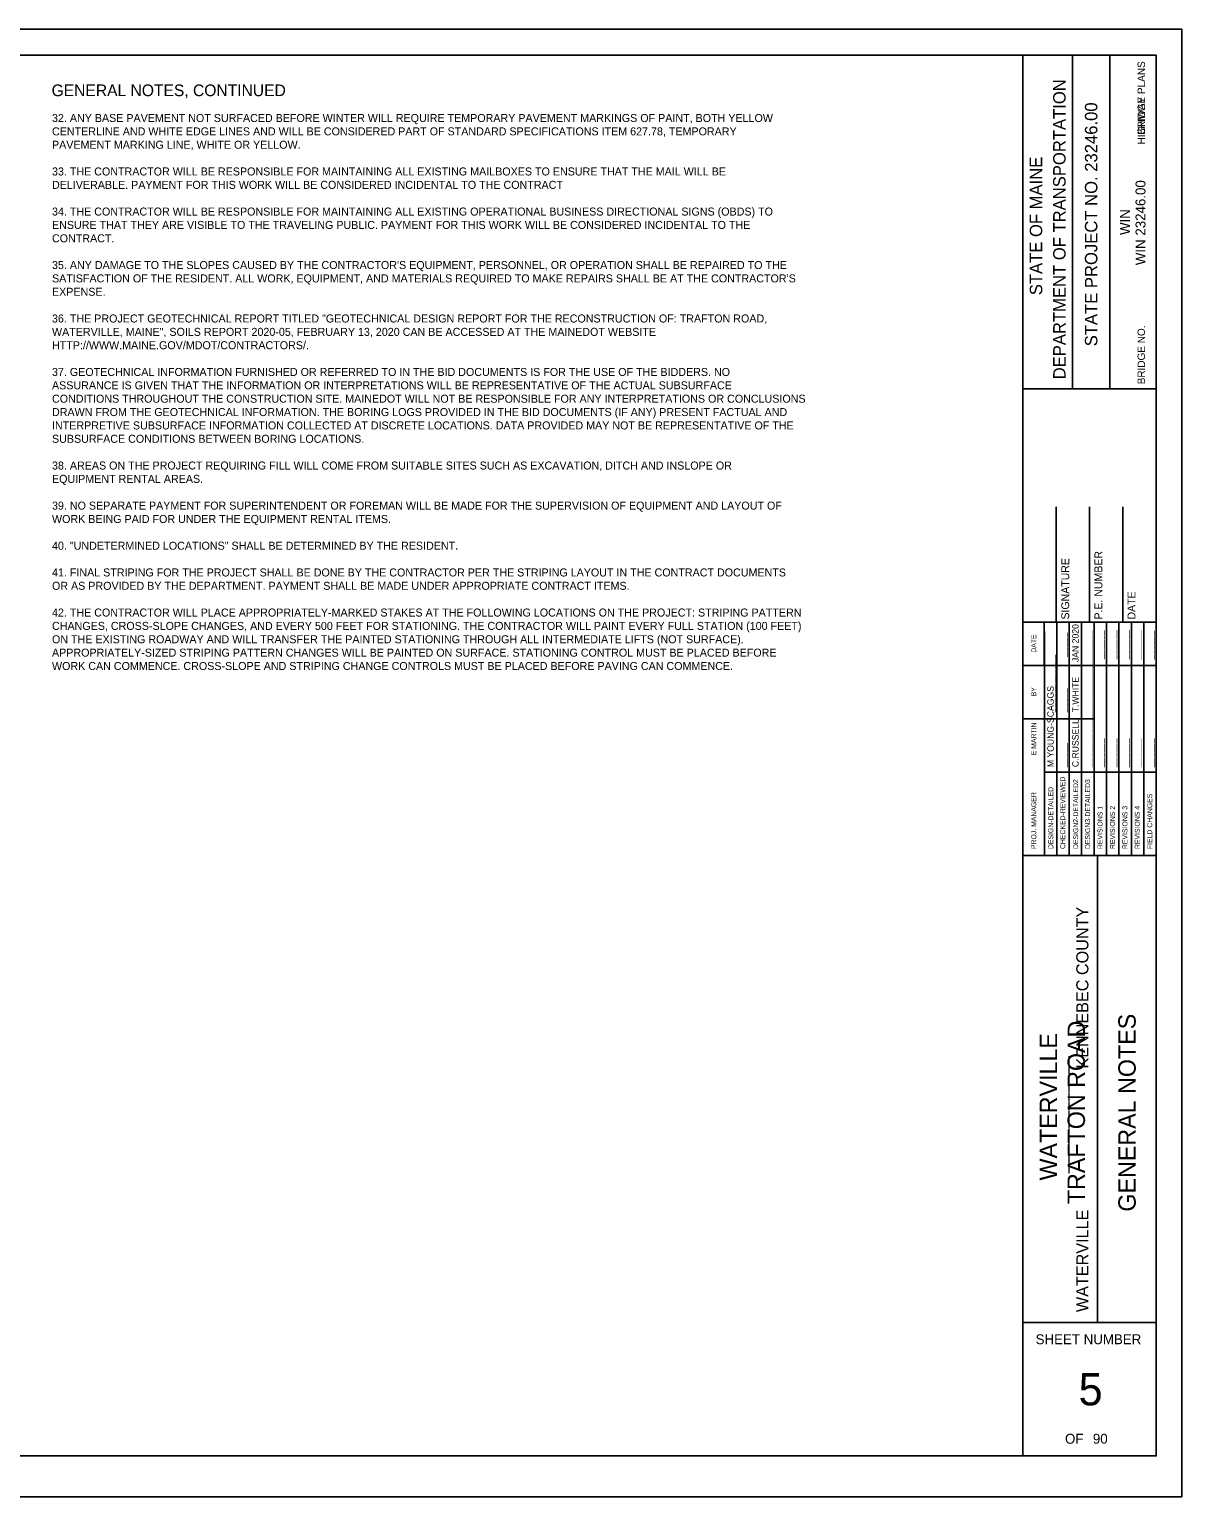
# Model space of a CAD drawing. Extents: x -0.17 to 2.66, y 2.06 to 3.89.
# Drawn here: x 1.225 to 2.664, y 2.057 to 3.89 of the extents above; entities that cross this region are included whole.
import ezdxf

# ---------------------------------------------------------------- set-up
doc = ezdxf.new("R2010")
doc.units = 0
for name, color, linetype in [('ANNOTATION', 7, 'Continuous'), ('BORDER', 7, 'Continuous'), ('BRIDGE_TITLE', 7, 'Continuous'), ('HIGHWAY_TITLE', 7, 'Continuous'), ('PLOT BOUNDARY', 7, 'Continuous')]:
    doc.layers.add(name, color=color, linetype=linetype)

msp = doc.modelspace()

# ---------------------------------------------------------------- linework, layer by layer
at = {"layer": 'BORDER'}
for p, q in [((2.4656, 2.1076), (2.4656, 3.8576)), ((2.5278, 3.4409), (2.5278, 3.8576)), ((2.5744, 3.4409), (2.5744, 3.8576)), ((2.4656, 3.4409), (2.6323, 3.4409)), ((2.5073, 3.1493), (2.5073, 3.2935)), ((2.549, 3.1493), (2.549, 3.2935)), ((2.5906, 3.1493), (2.5906, 3.2935)), ((2.4656, 3.1493), (2.6323, 3.1493)), ((2.4656, 2.8577), (2.6323, 2.8577)), ((2.5588, 2.2743), (2.5588, 2.8577)), ((2.4656, 2.2743), (2.6323, 2.2743))]:
    msp.add_line(p, q, dxfattribs=at)
msp.add_lwpolyline([(-0.0344, 3.8576), (2.6323, 3.8576), (2.6323, 2.1076), (-0.0344, 2.1076)], close=True, dxfattribs=at)
for points in [[(2.4925, 3.0952), (2.4925, 3.1493)], [(2.4926, 2.8577), (2.4926, 3.1376)], [(2.5081, 2.8577), (2.5081, 3.1493)], [(2.5236, 3.1493), (2.5236, 2.8577)], [(2.5391, 2.8577), (2.5391, 3.1493)], [(2.5547, 2.8577), (2.5547, 3.1493)], [(2.5702, 2.8577), (2.5702, 3.1493)], [(2.5857, 2.8577), (2.5857, 3.1493)], [(2.6013, 2.8577), (2.6013, 3.1493)], [(2.6168, 2.8577), (2.6168, 3.1493)], [(2.4656, 3.0952), (2.6323, 3.0952)], [(2.4656, 3.0285), (2.4926, 3.0285)], [(2.4925, 3.0285), (2.5547, 3.0285)], [(2.4925, 2.9618), (2.6323, 2.9618)]]:
    msp.add_lwpolyline(points, dxfattribs=at)
at = {"layer": 'PLOT BOUNDARY'}
msp.add_lwpolyline([(-0.1693, 2.0566), (2.6641, 2.0566), (2.6641, 3.89), (-0.1693, 3.89)], close=True, dxfattribs=at)

# ---------------------------------------------------------------- texts
at = {"layer": 'ANNOTATION'}
for s, height, p in [('GENERAL NOTES, CONTINUED', 0.014583, (1.2525, 3.8065)), ('32. ANY BASE PAVEMENT NOT SURFACED BEFORE WINTER WILL REQUIRE TEMPORARY PAVEMENT MARKINGS OF PAINT, BOTH YELLOW ', 0.01, (1.253, 3.7742)), ('CENTERLINE AND WHITE EDGE LINES AND WILL BE CONSIDERED PART OF STANDARD SPECIFICATIONS ITEM 627.78, TEMPORARY ', 0.01, (1.253, 3.7575)), ('PAVEMENT MARKING LINE, WHITE OR YELLOW.', 0.01, (1.253, 3.7408)), ('33. THE CONTRACTOR WILL BE RESPONSIBLE FOR MAINTAINING ALL EXISTING MAILBOXES TO ENSURE THAT THE MAIL WILL BE ', 0.01, (1.253, 3.7074)), ('DELIVERABLE. PAYMENT FOR THIS WORK WILL BE CONSIDERED INCIDENTAL TO THE CONTRACT', 0.01, (1.253, 3.6907)), ('34. THE CONTRACTOR WILL BE RESPONSIBLE FOR MAINTAINING ALL EXISTING OPERATIONAL BUSINESS DIRECTIONAL SIGNS (OBDS) TO ', 0.01, (1.253, 3.6573)), ('ENSURE THAT THEY ARE VISIBLE TO THE TRAVELING PUBLIC. PAYMENT FOR THIS WORK WILL BE CONSIDERED INCIDENTAL TO THE ', 0.01, (1.253, 3.6406)), ('CONTRACT.', 0.01, (1.253, 3.6239)), ("35. ANY DAMAGE TO THE SLOPES CAUSED BY THE CONTRACTOR'S EQUIPMENT, PERSONNEL, OR OPERATION SHALL BE REPAIRED TO THE ", 0.01, (1.253, 3.5905)), ("SATISFACTION OF THE RESIDENT. ALL WORK, EQUIPMENT, AND MATERIALS REQUIRED TO MAKE REPAIRS SHALL BE AT THE CONTRACTOR'S ", 0.01, (1.253, 3.5738)), ('EXPENSE. ', 0.01, (1.253, 3.5571)), ('36. THE PROJECT GEOTECHNICAL REPORT TITLED "GEOTECHNICAL DESIGN REPORT FOR THE RECONSTRUCTION OF: TRAFTON ROAD, ', 0.01, (1.253, 3.5237)), ('WATERVILLE, MAINE", SOILS REPORT 2020-05, FEBRUARY 13, 2020 CAN BE ACCESSED AT THE MAINEDOT WEBSITE ', 0.01, (1.253, 3.507)), ('HTTP://WWW.MAINE.GOV/MDOT/CONTRACTORS/.  ', 0.01, (1.253, 3.4903)), ('37. GEOTECHNICAL INFORMATION FURNISHED OR REFERRED TO IN THE BID DOCUMENTS IS FOR THE USE OF THE BIDDERS. NO ', 0.01, (1.253, 3.4569)), ('ASSURANCE IS GIVEN THAT THE INFORMATION OR INTERPRETATIONS WILL BE REPRESENTATIVE OF THE ACTUAL SUBSURFACE ', 0.01, (1.253, 3.4402)), ('CONDITIONS THROUGHOUT THE CONSTRUCTION SITE. MAINEDOT WILL NOT BE RESPONSIBLE FOR ANY INTERPRETATIONS OR CONCLUSIONS ', 0.01, (1.253, 3.4235)), ('DRAWN FROM THE GEOTECHNICAL INFORMATION. THE BORING LOGS PROVIDED IN THE BID DOCUMENTS (IF ANY) PRESENT FACTUAL AND ', 0.01, (1.253, 3.4068)), ('INTERPRETIVE SUBSURFACE INFORMATION COLLECTED AT DISCRETE LOCATIONS. DATA PROVIDED MAY NOT BE REPRESENTATIVE OF THE ', 0.01, (1.253, 3.3901)), ('SUBSURFACE CONDITIONS BETWEEN BORING LOCATIONS.', 0.01, (1.253, 3.3734)), ('38. AREAS ON THE PROJECT REQUIRING FILL WILL COME FROM SUITABLE SITES SUCH AS EXCAVATION, DITCH AND INSLOPE OR ', 0.01, (1.253, 3.34)), ('EQUIPMENT RENTAL AREAS.', 0.01, (1.253, 3.3233)), ('39. NO SEPARATE PAYMENT FOR SUPERINTENDENT OR FOREMAN WILL BE MADE FOR THE SUPERVISION OF EQUIPMENT AND LAYOUT OF ', 0.01, (1.253, 3.2899)), ('WORK BEING PAID FOR UNDER THE EQUIPMENT RENTAL ITEMS.', 0.01, (1.253, 3.2732)), ('40. "UNDETERMINED LOCATIONS" SHALL BE DETERMINED BY THE RESIDENT.', 0.01, (1.253, 3.2398)), ('41. FINAL STRIPING FOR THE PROJECT SHALL BE DONE BY THE CONTRACTOR PER THE STRIPING LAYOUT IN THE CONTRACT DOCUMENTS ', 0.01, (1.253, 3.2064)), ('OR AS PROVIDED BY THE DEPARTMENT. PAYMENT SHALL BE MADE UNDER APPROPRIATE CONTRACT ITEMS.', 0.01, (1.253, 3.1897)), ('42. THE CONTRACTOR WILL PLACE APPROPRIATELY-MARKED STAKES AT THE FOLLOWING LOCATIONS ON THE PROJECT: STRIPING PATTERN ', 0.01, (1.253, 3.1563)), ('CHANGES, CROSS-SLOPE CHANGES, AND EVERY 500 FEET FOR STATIONING. THE CONTRACTOR WILL PAINT EVERY FULL STATION (100 FEET) ', 0.01, (1.253, 3.1396)), ('ON THE EXISTING ROADWAY AND WILL TRANSFER THE PAINTED STATIONING THROUGH ALL INTERMEDIATE LIFTS (NOT SURFACE). ', 0.01, (1.253, 3.1229)), ('APPROPRIATELY-SIZED STRIPING PATTERN CHANGES WILL BE PAINTED ON SURFACE. STATIONING CONTROL MUST BE PLACED BEFORE ', 0.01, (1.253, 3.1062)), ('WORK CAN COMMENCE. CROSS-SLOPE AND STRIPING CHANGE CONTROLS MUST BE PLACED BEFORE PAVING CAN COMMENCE.', 0.01, (1.253, 3.0895))]:
    msp.add_text(s, height=height, dxfattribs=at).set_placement(p)
at = {"layer": 'BORDER'}
for s, height, p in [('DEPARTMENT OF TRANSPORTATION', 0.015529, (2.5191, 3.4527)), ('STATE PROJECT NO. 23246.00', 0.015529, (2.5588, 3.494)), ('STATE OF MAINE', 0.015529, (2.4899, 3.5578)), ('WIN 23246.00', 0.012421, (2.6189, 3.5953)), ('WIN', 0.01242, (2.5996, 3.6331)), ('SIGNATURE', 0.00984, (2.5236, 3.1526)), ('P.E. NUMBER', 0.009843, (2.565, 3.1526)), ('DATE', 0.00984, (2.6063, 3.1526)), ('_____', 0.00808, (2.5193, 3.1061)), ('JAN 2020', 0.00808, (2.5354, 3.0994)), ('______', 0.00808, (2.5503, 3.1031)), ('______', 0.00808, (2.5658, 3.1031)), ('______', 0.00808, (2.5814, 3.1032)), ('______', 0.00808, (2.5969, 3.1032)), ('______', 0.00808, (2.6124, 3.1027)), ('______', 0.00808, (2.6279, 3.1026)), ('DATE', 0.00619, (2.4824, 3.1111)), ('____________', 0.008076, (2.5043, 3.0366)), ('____________', 0.008076, (2.5503, 3.0366)), ('T.WHITE', 0.00808, (2.5354, 3.0366)), ('BY', 0.00619, (2.4824, 3.0566)), ('M YOUNG-SCAGGS', 0.008076, (2.5043, 2.9681)), ('_____', 0.00808, (2.5199, 3.0366)), ('C.RUSSELL', 0.00808, (2.5354, 2.9681)), ('____________', 0.008076, (2.5503, 2.9681)), ('E MARTIN', 0.00621, (2.4824, 2.983)), ('_____', 0.00808, (2.5193, 2.9681)), ('______', 0.00808, (2.5658, 2.9681)), ('______', 0.00808, (2.5814, 2.9681)), ('______', 0.00808, (2.5969, 2.9681)), ('______', 0.00808, (2.6124, 2.9681)), ('______', 0.00808, (2.6279, 2.9681)), ('CHECKED-REVIEWED', 0.006212, (2.5186, 2.8658)), ('PROJ. MANAGER', 0.006212, (2.4824, 2.8658)), ('DESIGN-DETAILED', 0.006212, (2.5037, 2.8658)), ('DESIGN2-DETAILED2', 0.006212, (2.5348, 2.8658)), ('DESIGN3-DETAILED3', 0.006212, (2.5497, 2.8658)), ('REVISIONS 1', 0.006212, (2.5652, 2.8658)), ('REVISIONS 2', 0.006212, (2.5808, 2.8658)), ('REVISIONS 3', 0.006212, (2.5963, 2.8658)), ('REVISIONS 4', 0.006212, (2.6118, 2.8658)), ('FIELD CHANGES', 0.006212, (2.6273, 2.8658)), ('GENERAL NOTES', 0.021738, (2.6067, 2.4128))]:
    msp.add_text(s, height=height, rotation=90, dxfattribs=at).set_placement(p)
for s, height, p in [('SHEET NUMBER', 0.012421, (2.4817, 2.2471)), ('5', 0.0403, (2.5354, 2.1707)), ('OF', 0.01242, (2.5184, 2.1228)), ('90', 0.01242, (2.5532, 2.1228))]:
    msp.add_text(s, height=height, dxfattribs=at).set_placement(p)
at = {"layer": 'BRIDGE_TITLE'}
for s, height, p in [('BRIDGE PLANS', 0.009317, (2.6183, 3.758)), ('BRIDGE NO.', 0.00932, (2.6183, 3.4465)), ('KENNEBEC COUNTY', 0.015119, (2.5476, 2.5915)), ('_____________', 0.015119, (2.5197, 2.4608)), ('WATERVILLE', 0.01512, (2.5476, 2.2872))]:
    msp.add_text(s, height=height, rotation=90, dxfattribs=at).set_placement(p)
at = {"layer": 'HIGHWAY_TITLE'}
for s, height, p in [('HIGHWAY PLANS', 0.009317, (2.6183, 3.7462)), ('TRAFTON ROAD', 0.021738, (2.5433, 2.4221)), ('WATERVILLE', 0.02174, (2.5085, 2.4517))]:
    msp.add_text(s, height=height, rotation=90, dxfattribs=at).set_placement(p)

doc.saveas('drawing.dxf')
